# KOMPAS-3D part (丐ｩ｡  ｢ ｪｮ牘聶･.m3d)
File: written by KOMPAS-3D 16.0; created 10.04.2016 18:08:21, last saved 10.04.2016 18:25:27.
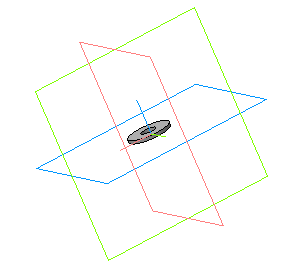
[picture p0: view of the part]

Referenced files in E:\Libs\PartLib\DATA\vault\Methods\Kompas\3D\: PLib_Washer_1_712.m3d
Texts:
  АД1 ГОСТ 4784-97
  Шайба A 4.37 ГОСТ 6958-78
  (-) Шайба A 4.37 ГОСТ 6958-78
